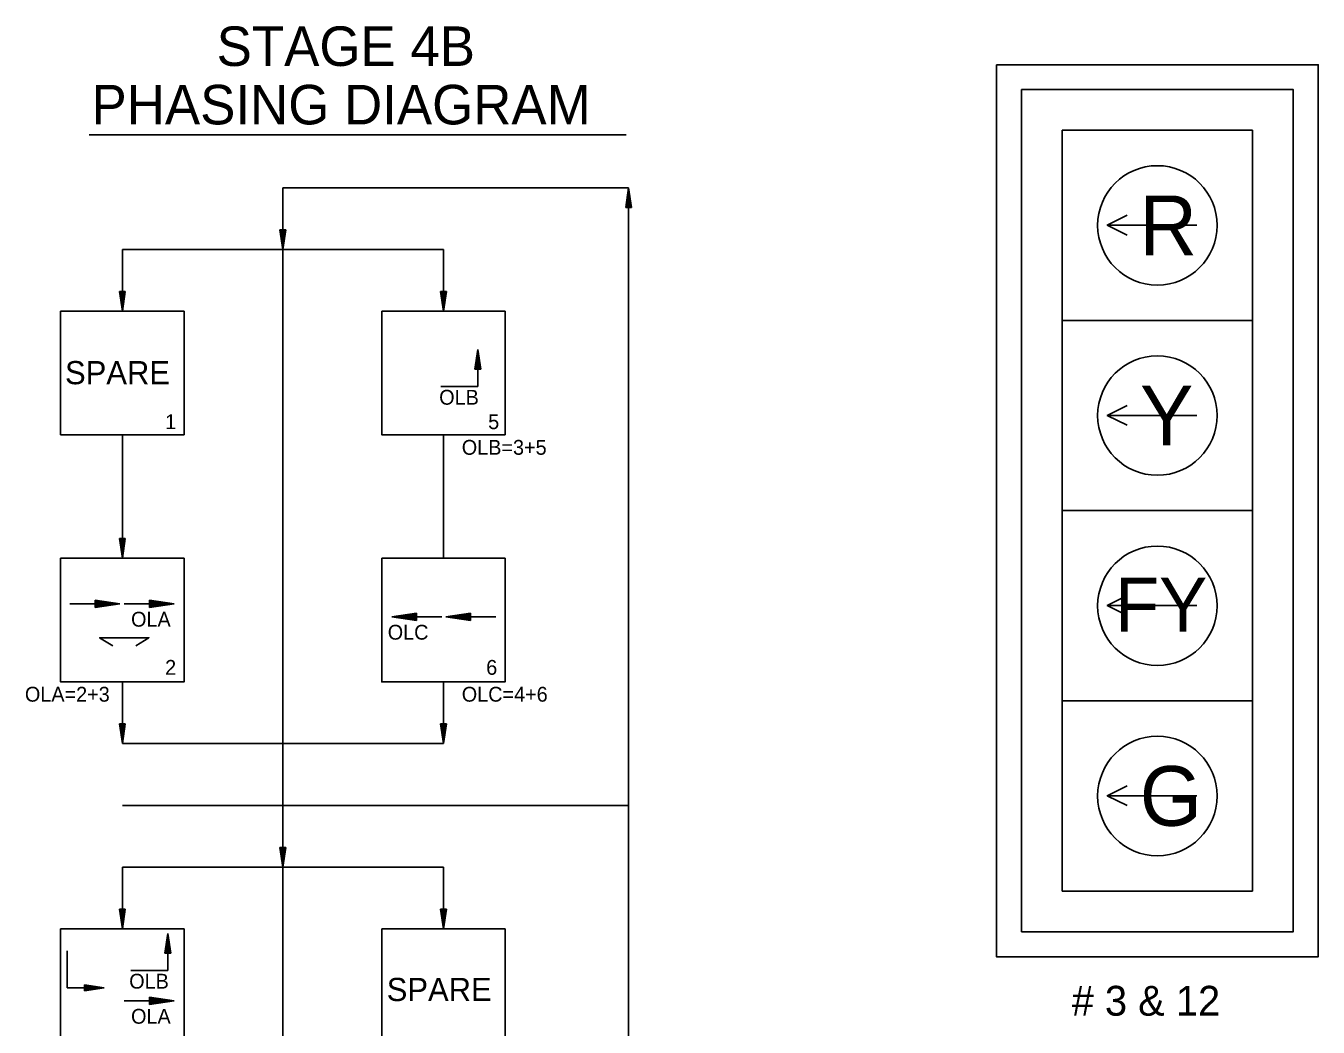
# Model space of a CAD drawing. Extents: x -218554 to 420030, y -565899 to -483460.
# Drawn here: x 418105.8 to 418287.9, y -565429.8 to -565288.9 of the extents above; entities that cross this region are included whole.
import ezdxf

# ---------------------------------------------------------------- set-up
doc = ezdxf.new("R2010")
doc.units = 0
for name, color, linetype in [('G-ANNO-STMP', 7, 'Continuous'), ('G-Border-Paper', 7, 'Continuous'), ('Level 57', 7, 'Continuous'), ('Level 61', 7, 'Continuous')]:
    doc.layers.add(name, color=color, linetype=linetype)

msp = doc.modelspace()

# ---------------------------------------------------------------- linework, layer by layer
at = {"layer": 'G-Border-Paper'}
for points in [[(418242.55, -565294.33), (418242.55, -565419.92), (418287.86, -565419.92), (418287.86, -565294.33), (418242.55, -565294.33)], [(418246.09, -565416.41), (418246.09, -565297.83), (418284.34, -565297.83), (418284.34, -565416.41), (418246.09, -565416.41)]]:
    msp.add_lwpolyline(points, dxfattribs=at)
at = {"layer": 'Level 57'}
for p, q in [((418114.78, -565304.2), (418190.38, -565304.2)), ((418142.05, -565494.27), (418142.05, -565311.65)), ((418142.05, -565311.65), (418190.74, -565311.65)), ((418190.33, -565314.43), (418190.74, -565311.65)), ((418190.4, -565314.43), (418190.74, -565312.12)), ((418190.74, -565311.65), (418190.74, -565494.27)), ((418191.16, -565314.43), (418190.74, -565311.65)), ((418191.09, -565314.43), (418190.74, -565312.12)), ((418190.47, -565314.43), (418190.74, -565312.59)), ((418190.54, -565314.43), (418190.74, -565313.06)), ((418190.61, -565314.43), (418190.74, -565313.53)), ((418190.68, -565314.43), (418190.74, -565313.99)), ((418191.02, -565314.43), (418190.74, -565312.59)), ((418190.95, -565314.43), (418190.74, -565313.06)), ((418190.88, -565314.43), (418190.74, -565313.53)), ((418190.81, -565314.43), (418190.74, -565313.99)), ((418190.33, -565314.43), (418191.16, -565314.43)), ((418141.63, -565317.56), (418142.05, -565320.35)), ((418142.46, -565317.56), (418141.63, -565317.56)), ((418141.7, -565317.56), (418142.05, -565319.88)), ((418141.77, -565317.56), (418142.05, -565319.4)), ((418141.84, -565317.56), (418142.05, -565318.94)), ((418141.91, -565317.56), (418142.05, -565318.47)), ((418141.98, -565317.56), (418142.05, -565318)), ((418142.46, -565317.56), (418142.05, -565320.35)), ((418142.18, -565317.56), (418142.05, -565318.47)), ((418142.32, -565317.56), (418142.05, -565319.4)), ((418142.39, -565317.56), (418142.05, -565319.88)), ((418142.25, -565317.56), (418142.05, -565318.94)), ((418142.11, -565317.56), (418142.05, -565318)), ((418119.44, -565329.04), (418119.44, -565320.35)), ((418119.44, -565320.35), (418164.66, -565320.35)), ((418164.66, -565329.04), (418164.66, -565320.35)), ((418119.02, -565326.26), (418119.44, -565329.04)), ((418119.85, -565326.26), (418119.02, -565326.26)), ((418119.09, -565326.26), (418119.44, -565328.58)), ((418119.16, -565326.26), (418119.44, -565328.1)), ((418119.23, -565326.26), (418119.44, -565327.64)), ((418119.3, -565326.26), (418119.44, -565327.17)), ((418119.37, -565326.26), (418119.44, -565326.7)), ((418119.85, -565326.26), (418119.44, -565329.04)), ((418119.57, -565326.26), (418119.44, -565327.17)), ((418119.71, -565326.26), (418119.44, -565328.1)), ((418119.78, -565326.26), (418119.44, -565328.58)), ((418119.64, -565326.26), (418119.44, -565327.64)), ((418119.5, -565326.26), (418119.44, -565326.7)), ((418164.24, -565326.26), (418164.66, -565329.04)), ((418165.07, -565326.26), (418164.24, -565326.26)), ((418164.31, -565326.26), (418164.66, -565328.58)), ((418164.38, -565326.26), (418164.66, -565328.1)), ((418164.45, -565326.26), (418164.66, -565327.64)), ((418164.52, -565326.26), (418164.66, -565327.17)), ((418164.59, -565326.26), (418164.66, -565326.7)), ((418165.07, -565326.26), (418164.66, -565329.04)), ((418164.79, -565326.26), (418164.66, -565327.17)), ((418164.93, -565326.26), (418164.66, -565328.1)), ((418165, -565326.26), (418164.66, -565328.58)), ((418164.86, -565326.26), (418164.66, -565327.64)), ((418164.72, -565326.26), (418164.66, -565326.7)), ((418169.09, -565337.22), (418169.5, -565334.44)), ((418169.5, -565334.9), (418169.16, -565337.22)), ((418169.23, -565337.22), (418169.5, -565335.38)), ((418169.5, -565335.85), (418169.3, -565337.22)), ((418169.5, -565339.66), (418169.5, -565334.44)), ((418169.5, -565334.44), (418169.92, -565337.22)), ((418169.85, -565337.22), (418169.5, -565334.9)), ((418169.5, -565335.38), (418169.78, -565337.22)), ((418169.71, -565337.22), (418169.5, -565335.85)), ((418169.09, -565337.22), (418169.92, -565337.22)), ((418169.37, -565337.22), (418169.5, -565336.32)), ((418169.5, -565336.78), (418169.44, -565337.22)), ((418169.5, -565336.32), (418169.64, -565337.22)), ((418169.57, -565337.22), (418169.5, -565336.78)), ((418164.29, -565339.66), (418169.5, -565339.66)), ((418119.44, -565363.83), (418119.44, -565346.44)), ((418164.66, -565363.83), (418164.66, -565346.44)), ((418119.02, -565361.04), (418119.44, -565363.83)), ((418119.85, -565361.04), (418119.02, -565361.04)), ((418119.09, -565361.04), (418119.44, -565363.36)), ((418119.16, -565361.04), (418119.44, -565362.88)), ((418119.23, -565361.04), (418119.44, -565362.42)), ((418119.3, -565361.04), (418119.44, -565361.95)), ((418119.37, -565361.04), (418119.44, -565361.48)), ((418119.85, -565361.04), (418119.44, -565363.83)), ((418119.57, -565361.04), (418119.44, -565361.95)), ((418119.71, -565361.04), (418119.44, -565362.88)), ((418119.78, -565361.04), (418119.44, -565363.36)), ((418119.64, -565361.04), (418119.44, -565362.42)), ((418119.5, -565361.04), (418119.44, -565361.48)), ((418112.05, -565370.24), (418119.1, -565370.24)), ((418119.1, -565370.24), (418115.62, -565369.72)), ((418115.62, -565370.76), (418115.62, -565369.72)), ((418115.62, -565369.8), (418118.52, -565370.24)), ((418117.92, -565370.24), (418115.62, -565369.89)), ((418115.62, -565369.98), (418117.34, -565370.24)), ((418116.75, -565370.24), (418115.62, -565370.07)), ((418115.62, -565370.16), (418116.17, -565370.24)), ((418116.17, -565370.24), (418115.62, -565370.32)), ((418115.62, -565370.41), (418116.75, -565370.24)), ((418117.34, -565370.24), (418115.62, -565370.5)), ((418115.62, -565370.58), (418117.92, -565370.24)), ((418118.52, -565370.24), (418115.62, -565370.67)), ((418115.62, -565370.76), (418119.1, -565370.24)), ((418119.67, -565370.24), (418126.72, -565370.24)), ((418126.72, -565370.24), (418123.24, -565369.72)), ((418123.24, -565370.76), (418123.24, -565369.72)), ((418123.24, -565369.8), (418126.14, -565370.24)), ((418125.54, -565370.24), (418123.24, -565369.89)), ((418123.24, -565369.98), (418124.96, -565370.24)), ((418124.37, -565370.24), (418123.24, -565370.07)), ((418123.24, -565370.16), (418123.79, -565370.24)), ((418123.79, -565370.24), (418123.24, -565370.32)), ((418123.24, -565370.41), (418124.37, -565370.24)), ((418124.96, -565370.24), (418123.24, -565370.5)), ((418123.24, -565370.58), (418125.54, -565370.24)), ((418126.14, -565370.24), (418123.24, -565370.67)), ((418123.24, -565370.76), (418126.72, -565370.24)), ((418157.37, -565372.07), (418160.85, -565371.55)), ((418164.42, -565372.07), (418157.37, -565372.07)), ((418160.85, -565372.59), (418157.37, -565372.07)), ((418160.85, -565371.64), (418157.96, -565372.07)), ((418157.96, -565372.07), (418160.85, -565372.5)), ((418158.55, -565372.07), (418160.85, -565371.72)), ((418160.85, -565372.42), (418158.55, -565372.07)), ((418160.85, -565371.81), (418159.13, -565372.07)), ((418159.13, -565372.07), (418160.85, -565372.33)), ((418159.72, -565372.07), (418160.85, -565371.9)), ((418160.85, -565372.24), (418159.72, -565372.07)), ((418160.85, -565371.99), (418160.3, -565372.07)), ((418160.3, -565372.07), (418160.85, -565372.15)), ((418160.85, -565372.59), (418160.85, -565371.55)), ((418165, -565372.07), (418168.47, -565371.55)), ((418172.05, -565372.07), (418165, -565372.07)), ((418168.47, -565372.59), (418165, -565372.07)), ((418168.47, -565371.64), (418165.58, -565372.07)), ((418165.58, -565372.07), (418168.47, -565372.5)), ((418166.17, -565372.07), (418168.47, -565371.72)), ((418168.47, -565372.42), (418166.17, -565372.07)), ((418168.47, -565371.81), (418166.75, -565372.07)), ((418166.75, -565372.07), (418168.47, -565372.33)), ((418167.34, -565372.07), (418168.47, -565371.9)), ((418168.47, -565372.24), (418167.34, -565372.07)), ((418168.47, -565371.99), (418167.92, -565372.07)), ((418167.92, -565372.07), (418168.47, -565372.15)), ((418168.47, -565372.59), (418168.47, -565371.55)), ((418119.44, -565389.92), (418119.44, -565381.22)), ((418164.66, -565389.92), (418164.66, -565381.22)), ((418164.66, -565389.92), (418164.66, -565381.22)), ((418119.02, -565387.13), (418119.44, -565389.92)), ((418119.85, -565387.13), (418119.02, -565387.13)), ((418119.09, -565387.13), (418119.44, -565389.45)), ((418119.16, -565387.13), (418119.44, -565388.97)), ((418119.23, -565387.13), (418119.44, -565388.51)), ((418119.3, -565387.13), (418119.44, -565388.04)), ((418119.37, -565387.13), (418119.44, -565387.57)), ((418119.85, -565387.13), (418119.44, -565389.92)), ((418119.57, -565387.13), (418119.44, -565388.04)), ((418119.71, -565387.13), (418119.44, -565388.97)), ((418119.78, -565387.13), (418119.44, -565389.45)), ((418119.64, -565387.13), (418119.44, -565388.51)), ((418119.5, -565387.13), (418119.44, -565387.57)), ((418164.24, -565387.13), (418164.66, -565389.92)), ((418165.07, -565387.13), (418164.24, -565387.13)), ((418164.24, -565387.13), (418164.66, -565389.92)), ((418165.07, -565387.13), (418164.24, -565387.13)), ((418164.31, -565387.13), (418164.66, -565389.45)), ((418164.31, -565387.13), (418164.66, -565389.45)), ((418164.38, -565387.13), (418164.66, -565388.97)), ((418164.38, -565387.13), (418164.66, -565388.97)), ((418164.45, -565387.13), (418164.66, -565388.51)), ((418164.45, -565387.13), (418164.66, -565388.51)), ((418164.52, -565387.13), (418164.66, -565388.04)), ((418164.52, -565387.13), (418164.66, -565388.04)), ((418164.59, -565387.13), (418164.66, -565387.57)), ((418164.59, -565387.13), (418164.66, -565387.57)), ((418165.07, -565387.13), (418164.66, -565389.92)), ((418164.79, -565387.13), (418164.66, -565388.04)), ((418164.93, -565387.13), (418164.66, -565388.97)), ((418165, -565387.13), (418164.66, -565389.45)), ((418164.86, -565387.13), (418164.66, -565388.51)), ((418164.72, -565387.13), (418164.66, -565387.57)), ((418165.07, -565387.13), (418164.66, -565389.92)), ((418164.79, -565387.13), (418164.66, -565388.04)), ((418164.93, -565387.13), (418164.66, -565388.97)), ((418165, -565387.13), (418164.66, -565389.45)), ((418164.86, -565387.13), (418164.66, -565388.51)), ((418164.72, -565387.13), (418164.66, -565387.57)), ((418119.44, -565389.92), (418164.66, -565389.92)), ((418119.44, -565398.61), (418190.74, -565398.61)), ((418141.63, -565404.53), (418142.05, -565407.31)), ((418142.46, -565404.53), (418141.63, -565404.53)), ((418141.7, -565404.53), (418142.05, -565406.84)), ((418141.77, -565404.53), (418142.05, -565406.36)), ((418141.84, -565404.53), (418142.05, -565405.9)), ((418141.91, -565404.53), (418142.05, -565405.43)), ((418141.98, -565404.53), (418142.05, -565404.96)), ((418142.46, -565404.53), (418142.05, -565407.31)), ((418142.18, -565404.53), (418142.05, -565405.43)), ((418142.32, -565404.53), (418142.05, -565406.36)), ((418142.39, -565404.53), (418142.05, -565406.84)), ((418142.25, -565404.53), (418142.05, -565405.9)), ((418142.11, -565404.53), (418142.05, -565404.96)), ((418119.44, -565407.31), (418164.66, -565407.31)), ((418119.44, -565416), (418119.44, -565407.31)), ((418164.66, -565416), (418164.66, -565407.31)), ((418119.02, -565413.22), (418119.44, -565416)), ((418119.85, -565413.22), (418119.02, -565413.22)), ((418119.09, -565413.22), (418119.44, -565415.54)), ((418119.16, -565413.22), (418119.44, -565415.06)), ((418119.23, -565413.22), (418119.44, -565414.6)), ((418119.3, -565413.22), (418119.44, -565414.13)), ((418119.37, -565413.22), (418119.44, -565413.66)), ((418119.85, -565413.22), (418119.44, -565416)), ((418119.57, -565413.22), (418119.44, -565414.13)), ((418119.71, -565413.22), (418119.44, -565415.06)), ((418119.78, -565413.22), (418119.44, -565415.54)), ((418119.64, -565413.22), (418119.44, -565414.6)), ((418119.5, -565413.22), (418119.44, -565413.66)), ((418164.24, -565413.22), (418164.66, -565416)), ((418165.07, -565413.22), (418164.24, -565413.22)), ((418164.31, -565413.22), (418164.66, -565415.54)), ((418164.38, -565413.22), (418164.66, -565415.06)), ((418164.45, -565413.22), (418164.66, -565414.6)), ((418164.52, -565413.22), (418164.66, -565414.13)), ((418164.59, -565413.22), (418164.66, -565413.66)), ((418165.07, -565413.22), (418164.66, -565416)), ((418164.79, -565413.22), (418164.66, -565414.13)), ((418164.93, -565413.22), (418164.66, -565415.06)), ((418165, -565413.22), (418164.66, -565415.54)), ((418164.86, -565413.22), (418164.66, -565414.6)), ((418164.72, -565413.22), (418164.66, -565413.66)), ((418125.42, -565419.43), (418125.84, -565416.65)), ((418125.84, -565417.11), (418125.49, -565419.43)), ((418125.56, -565419.43), (418125.84, -565417.59)), ((418125.84, -565421.86), (418125.84, -565416.65)), ((418125.84, -565416.65), (418126.26, -565419.43)), ((418126.19, -565419.43), (418125.84, -565417.11)), ((418125.84, -565417.59), (418126.12, -565419.43)), ((418111.65, -565419.1), (418111.65, -565424.32)), ((418125.42, -565419.43), (418126.26, -565419.43)), ((418125.84, -565418.05), (418125.63, -565419.43)), ((418125.71, -565419.43), (418125.84, -565418.52)), ((418125.84, -565418.99), (418125.78, -565419.43)), ((418126.05, -565419.43), (418125.84, -565418.05)), ((418125.84, -565418.52), (418125.98, -565419.43)), ((418125.91, -565419.43), (418125.84, -565418.99)), ((418120.62, -565421.86), (418125.84, -565421.86)), ((418111.65, -565424.32), (418116.87, -565424.32)), ((418114.09, -565423.9), (418116.87, -565424.32)), ((418114.09, -565423.9), (418114.09, -565424.74)), ((418116.4, -565424.32), (418114.09, -565423.97)), ((418114.09, -565424.04), (418115.92, -565424.32)), ((418115.46, -565424.32), (418114.09, -565424.11)), ((418114.09, -565424.18), (418114.99, -565424.32)), ((418114.52, -565424.32), (418114.09, -565424.25)), ((418116.87, -565424.32), (418114.09, -565424.74)), ((418114.09, -565424.67), (418116.4, -565424.32)), ((418115.92, -565424.32), (418114.09, -565424.6)), ((418114.09, -565424.53), (418115.46, -565424.32)), ((418114.99, -565424.32), (418114.09, -565424.46)), ((418114.09, -565424.38), (418114.52, -565424.32)), ((418119.67, -565426.14), (418126.72, -565426.14)), ((418126.72, -565426.14), (418123.24, -565425.62)), ((418123.24, -565426.67), (418123.24, -565425.62)), ((418123.24, -565425.71), (418126.14, -565426.14)), ((418125.54, -565426.14), (418123.24, -565425.8)), ((418123.24, -565425.88), (418124.96, -565426.14)), ((418124.37, -565426.14), (418123.24, -565425.97)), ((418123.24, -565426.06), (418123.79, -565426.14)), ((418123.79, -565426.14), (418123.24, -565426.23)), ((418123.24, -565426.31), (418124.37, -565426.14)), ((418124.96, -565426.14), (418123.24, -565426.4)), ((418123.24, -565426.49), (418125.54, -565426.14)), ((418126.14, -565426.14), (418123.24, -565426.58)), ((418123.24, -565426.67), (418126.72, -565426.14))]:
    msp.add_line(p, q, dxfattribs=at)
for points in [[(418110.74, -565329.04), (418128.13, -565329.04), (418128.13, -565346.44), (418110.74, -565346.44)], [(418155.96, -565329.04), (418173.35, -565329.04), (418173.35, -565346.44), (418155.96, -565346.44)], [(418110.74, -565363.83), (418128.13, -565363.83), (418128.13, -565381.22), (418110.74, -565381.22)], [(418155.96, -565363.83), (418173.35, -565363.83), (418173.35, -565381.22), (418155.96, -565381.22)], [(418110.74, -565416), (418128.13, -565416), (418128.13, -565433.4), (418110.74, -565433.4)], [(418155.96, -565416), (418173.35, -565416), (418173.35, -565433.4), (418155.96, -565433.4)]]:
    msp.add_lwpolyline(points, close=True, dxfattribs=at)
msp.add_lwpolyline([(418118.08, -565376.17), (418116.22, -565375.01), (418123.18, -565375.01), (418121.33, -565376.17)], dxfattribs=at)
at = {"layer": 'Level 61'}
for p, q in [((418251.82, -565303.57), (418278.6, -565303.57)), ((418251.82, -565303.57), (418251.82, -565330.35)), ((418278.6, -565303.57), (418278.6, -565330.35)), ((418270.76, -565316.92), (418258.14, -565316.92)), ((418251.82, -565330.35), (418278.6, -565330.35)), ((418251.82, -565330.35), (418251.82, -565357.12)), ((418278.6, -565330.35), (418278.6, -565357.12)), ((418270.76, -565343.7), (418258.14, -565343.7)), ((418251.82, -565357.12), (418278.6, -565357.12)), ((418251.82, -565357.12), (418251.82, -565383.9)), ((418278.6, -565357.12), (418278.6, -565383.9)), ((418270.76, -565370.47), (418258.14, -565370.47)), ((418251.82, -565383.9), (418278.6, -565383.9)), ((418251.82, -565383.9), (418251.82, -565410.68)), ((418278.6, -565383.9), (418278.6, -565410.68)), ((418270.76, -565397.25), (418258.14, -565397.25)), ((418251.82, -565410.68), (418278.6, -565410.68))]:
    msp.add_line(p, q, dxfattribs=at)
msp.add_lwpolyline([(418284.34, -565297.83), (418246.09, -565297.83), (418246.09, -565416.41), (418284.34, -565416.41)], close=True, dxfattribs=at)
for points in [[(418260.94, -565315.52), (418258.14, -565316.92), (418260.94, -565318.32)], [(418260.94, -565342.3), (418258.14, -565343.7), (418260.94, -565345.1)], [(418260.94, -565369.07), (418258.14, -565370.47), (418260.94, -565371.88)], [(418260.94, -565395.85), (418258.14, -565397.25), (418260.94, -565398.65)]]:
    msp.add_lwpolyline(points, dxfattribs=at)
for centre in [(418265.21, -565316.96), (418265.21, -565343.73), (418265.21, -565370.51), (418265.21, -565397.29)]:
    msp.add_circle(centre, 8.41, dxfattribs=at)

# ---------------------------------------------------------------- texts
at = {"layer": 'G-ANNO-STMP'}
msp.add_text('# 3 & 12', height=4.2, dxfattribs=at).set_placement((418253.14, -565428.22))
at = {"layer": 'Level 57'}
for s, height, p in [('STAGE 4B', 5.565, (418132.71, -565294.51)), ('PHASING DIAGRAM', 5.5655, (418115.09, -565302.74)), ('SPARE', 3.261, (418111.36, -565339.32)), ('OLB', 2.087, (418164.06, -565342.2)), ('1', 2.09, (418125.46, -565345.64)), ('5', 2.09, (418170.96, -565345.64)), ('OLB=3+5', 2.087, (418167.24, -565349.25)), ('OLA', 2.087, (418120.66, -565373.45)), ('OLC', 2.087, (418156.81, -565375.28)), ('2', 2.09, (418125.46, -565380.23)), ('6', 2.09, (418170.68, -565380.23)), ('OLA=2+3', 2.087, (418105.71, -565384.01)), ('OLC=4+6', 2.087, (418167.24, -565384.01)), ('OLB', 2.087, (418120.4, -565424.41)), ('SPARE', 3.261, (418156.67, -565426.16)), ('OLA', 2.087, (418120.66, -565429.35))]:
    msp.add_text(s, height=height, dxfattribs=at).set_placement(p)
at = {"layer": 'Level 61'}
for s, height, p in [('R', 8.41, (418262.67, -565321.16)), ('Y', 8.41, (418262.77, -565347.94)), ('FY', 7.605, (418259.24, -565374.17)), ('G', 8.41, (418262.74, -565401.49))]:
    msp.add_text(s, height=height, dxfattribs=at).set_placement(p)

doc.saveas('drawing.dxf')
